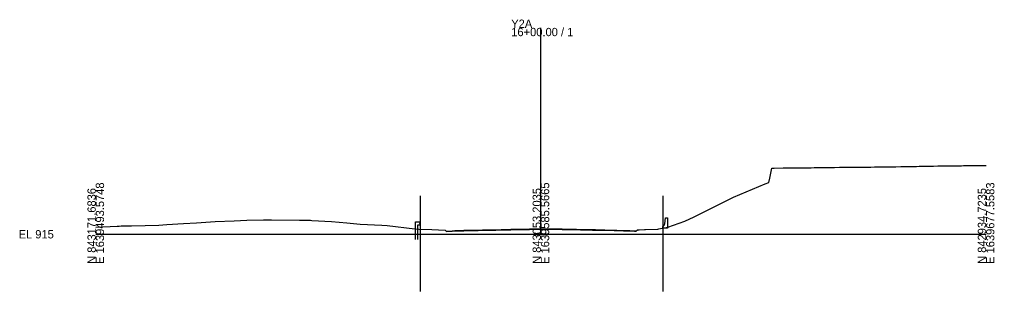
# Model space of a CAD drawing. Extents: x -26 to 303, y -10 to 10517.
# Drawn here: x -25.7 to 302.8, y 5480.7 to 5572.5 of the extents above; entities that cross this region are included whole.
import ezdxf

# ---------------------------------------------------------------- set-up
doc = ezdxf.new("R2010")
doc.units = 0
for name, color, linetype in [('Exist Cross Section Cell', 7, 'Continuous'), ('Exist XS Center Line Elevation Label', 7, 'Continuous'), ('Exist XS Ground Line', 7, 'Continuous'), ('Prop CMT Guardrail Widen Shoulder', 7, 'Continuous'), ('Prop CMT Pvmt Surface Overlay', 7, 'Continuous'), ('Scratch_Level_0', 7, 'Continuous'), ('Typical Median Barrier CELL', 7, 'Continuous')]:
    doc.layers.add(name, color=color, linetype=linetype)

msp = doc.modelspace()

# ---------------------------------------------------------------- linework, layer by layer
at = {"layer": 'Exist Cross Section Cell'}
for p, q in [((150, 5500), (150, 5569.65)), ((0, 5500), (150, 5500)), ((150, 5500), (300, 5500))]:
    msp.add_line(p, q, dxfattribs=at)
at = {"layer": 'Exist XS Ground Line'}
msp.add_lwpolyline([(0, 5502.45), (7.25, 5502.74), (7.9, 5502.77), (8.6, 5502.8), (12.03, 5502.87), (21.27, 5503.12), (23.92, 5503.26), (29.56, 5503.69), (33.93, 5503.9), (40.23, 5504.31), (46.59, 5504.57), (50.94, 5504.76), (56.54, 5504.86), (59.25, 5504.91), (68.67, 5504.76), (71.91, 5504.74), (72.32, 5504.72), (72.84, 5504.67), (79.45, 5504.3), (84.57, 5503.89), (89.15, 5503.44), (96.42, 5503.11), (98.16, 5502.96), (107.56, 5501.84), (108.86, 5501.72), (113.29, 5501.58), (117.7, 5501.43), (118.15, 5500.96), (120.08, 5501.07), (121, 5501.12), (121.59, 5501.16), (122.58, 5501.18), (123.37, 5501.19), (123.99, 5501.2), (125.15, 5501.23), (127.15, 5501.28), (128.88, 5501.31), (130.32, 5501.33), (130.79, 5501.34), (131.63, 5501.35), (132.69, 5501.36), (133.48, 5501.37), (134.06, 5501.38), (134.81, 5501.42), (136.65, 5501.49), (138.89, 5501.53), (139.41, 5501.54), (139.81, 5501.55), (140.6, 5501.56), (142.25, 5501.6), (142.58, 5501.61), (142.98, 5501.63), (144.75, 5501.65), (146.14, 5501.66), (146.63, 5501.67), (147.93, 5501.69), (149.31, 5501.69), (150, 5501.69), (151.11, 5501.7), (151.88, 5501.7), (152.47, 5501.7), (155.19, 5501.69), (155.64, 5501.69), (157.2, 5501.65), (158.25, 5501.62), (159.27, 5501.6), (160.79, 5501.58), (161.97, 5501.57), (163.34, 5501.53), (165.13, 5501.49), (166.13, 5501.48), (167.42, 5501.44), (168.08, 5501.43), (168.43, 5501.44), (168.87, 5501.43), (171.5, 5501.34), (174.63, 5501.28), (175.04, 5501.26), (175.57, 5501.24), (177.79, 5501.18), (179.41, 5501.13), (179.97, 5501.11), (181.53, 5501.02), (181.94, 5501), (182.57, 5501.48), (183.15, 5501.51), (184.9, 5501.61), (185.22, 5501.62), (189.41, 5501.73), (189.77, 5501.8), (192.81, 5502.45), (198.46, 5504.44), (201.65, 5505.93), (210.86, 5510.47), (214.95, 5512.5), (225.62, 5516.98), (226.81, 5517.49), (227.12, 5518.96), (227.84, 5522.33), (228.57, 5522.34), (231.6, 5522.38), (232.64, 5522.39), (234.77, 5522.41), (236.15, 5522.42), (236.72, 5522.42), (237.4, 5522.43), (237.93, 5522.43), (239.34, 5522.45), (240.27, 5522.46), (241.09, 5522.46), (242.04, 5522.48), (244.53, 5522.49), (244.87, 5522.49), (246.31, 5522.53), (247.43, 5522.53), (248.95, 5522.55), (250.59, 5522.59), (251.66, 5522.6), (253.03, 5522.63), (253.44, 5522.63), (253.76, 5522.64), (255.22, 5522.65), (257.1, 5522.65), (258.78, 5522.67), (260.09, 5522.67), (260.67, 5522.67), (261.18, 5522.68), (262.35, 5522.71), (263.25, 5522.73), (263.74, 5522.74), (265.04, 5522.75), (265.81, 5522.76), (266.49, 5522.77), (269.58, 5522.8), (271.25, 5522.83), (273.04, 5522.86), (273.41, 5522.86), (275.91, 5522.91), (276.6, 5522.92), (277.48, 5522.94), (278.38, 5522.95), (279.08, 5522.97), (280.16, 5522.98), (281.56, 5523.01), (282.24, 5523.02), (283.73, 5523.04), (285.64, 5523.07), (288.57, 5523.12), (289.25, 5523.12), (291.76, 5523.15), (292.34, 5523.16), (294.38, 5523.17), (294.9, 5523.17), (296.2, 5523.19), (298.07, 5523.19), (300, 5523.22)], dxfattribs=at)
at = {"layer": 'Prop CMT Guardrail Widen Shoulder'}
for points in [[(107.76, 5498.2), (107.76, 5504.2)], [(107.76, 5504.2), (109.09, 5504.2), (109.36, 5503.91)], [(109.36, 5503.32), (109.09, 5503.03), (108.42, 5503.03)], [(108.42, 5503.03), (108.42, 5498.2)], [(109.36, 5503.91), (109.09, 5503.62)], [(109.09, 5503.62), (109.36, 5503.32)]]:
    msp.add_lwpolyline(points, dxfattribs=at)
at = {"layer": 'Prop CMT Pvmt Surface Overlay'}
msp.add_lwpolyline([(118.04, 5501.07), (120.07, 5501.19), (120.99, 5501.24), (121.59, 5501.28), (122.58, 5501.3), (123.37, 5501.32), (123.98, 5501.33), (125.15, 5501.35), (127.15, 5501.4), (128.88, 5501.44), (130.32, 5501.46), (130.79, 5501.46), (131.63, 5501.47), (132.69, 5501.49), (133.48, 5501.49), (134.06, 5501.51), (134.8, 5501.54), (136.64, 5501.61), (138.88, 5501.65), (139.41, 5501.66), (139.81, 5501.67), (140.6, 5501.69), (142.25, 5501.72), (142.57, 5501.73), (142.97, 5501.76), (144.75, 5501.77), (146.14, 5501.79), (146.63, 5501.79), (147.93, 5501.81), (149.31, 5501.82), (151.11, 5501.82), (152.47, 5501.82), (155.19, 5501.82), (155.64, 5501.81), (157.2, 5501.78), (158.25, 5501.75), (159.27, 5501.73), (160.79, 5501.7), (161.97, 5501.69), (165.14, 5501.61), (166.14, 5501.6), (167.42, 5501.57), (168.08, 5501.56), (168.43, 5501.56), (168.87, 5501.55), (171.5, 5501.46), (174.63, 5501.4), (175.05, 5501.39), (175.58, 5501.37), (177.8, 5501.3), (179.41, 5501.26), (179.97, 5501.24), (181.54, 5501.15), (182.09, 5501.12)], dxfattribs=at)
at = {"layer": 'Scratch_Level_0'}
for p, q in [((109.36, 5513.01), (109.36, 5480.68)), ((191.13, 5513.01), (191.13, 5480.68)), ((109.36, 5503.91), (109.36, 5501.7))]:
    msp.add_line(p, q, dxfattribs=at)
at = {"layer": 'Typical Median Barrier CELL'}
for p, q in [((191.13, 5502.51), (191.59, 5503.17)), ((191.74, 5503.55), (191.96, 5505.51)), ((191.96, 5505.51), (192.63, 5505.51)), ((192.63, 5505.51), (192.63, 5502.09)), ((191.13, 5502.09), (191.13, 5502.51)), ((192.63, 5502.09), (191.13, 5502.09))]:
    msp.add_line(p, q, dxfattribs=at)
msp.add_arc((190.91, 5503.64), 0.833, 325.0039, 353.9447, dxfattribs=at)

# ---------------------------------------------------------------- texts
at = {"layer": 'Exist Cross Section Cell'}
for s, p in [('Y2A', (140, 5569.65)), ('16+00.00 / 1', (140, 5566.85)), ('EL 915', (-26, 5498.6))]:
    msp.add_text(s, height=2.8, dxfattribs=at).set_placement(p)
for s, p in [('E 1639493.5748', (2.8, 5490)), ('E 1639585.5665', (152.8, 5490)), ('E 1639677.5583', (302.8, 5490)), ('N 843171.6836', (0, 5490)), ('N 843053.2035', (150, 5490)), ('N 842934.7235', (300, 5490))]:
    msp.add_text(s, height=2.8, rotation=90, dxfattribs=at).set_placement(p)
at = {"layer": 'Exist XS Center Line Elevation Label'}
msp.add_text('916.69', height=1, dxfattribs=at).set_placement((147.87, 5499.32))

doc.saveas('drawing.dxf')
